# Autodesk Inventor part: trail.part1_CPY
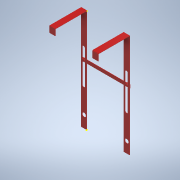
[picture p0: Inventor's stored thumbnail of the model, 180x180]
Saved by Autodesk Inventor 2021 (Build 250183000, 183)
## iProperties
Created: 2021-07
Part Number: trail.part1_CPY
Material: PMMA Plastic
Document SubType Name: Sheet Metal
Designer: CHIRAG
Density: 1.188 g/cm^3
Sheet Metal Rule: Default
Appearance: Red
Author: CHIRAG
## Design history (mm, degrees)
sketch "Sketch1"
  geometry: 1 further point
sketch "Sketch2"
  geometry: L1 (0, 0)-(-45.905, 0); L2 (-45.905, 0)-(-45.905, 801.589); L3 (-45.905, 801.589)-(0, 801.589); L4 (0, 801.589)-(0, 0)
  constraints: 8 end point, 2 parallel, 1 horizontal, 1 perpendicular
extrude "Extrusion1" new body sketch "Sketch2" distance "d0" = 3; taper "d1" = 0 deg
sketch "Sketch6"
  geometry: C1 r 15 at (-21.624, 91.104); 1 further point
  constraints: 1 centre point
  dimensions: "d12" = 30 diameter of C1
extrude "Extrusion4" cut sketch "Sketch6" distance "d13" = 3; taper "d14" = 0 deg
sketch "Sketch7"
  geometry: L1 (-24.46, 286.783)-(-24.46, 544.143); L2 (-45.905, 801.589)-(-45.905, 0) reference; L3 (-13.802, 286.783)-(-13.802, 544.143); L4 (-35.118, 544.143)-(-35.118, 286.783); A1 r 10.658 centre (-24.46, 286.783) between (-35.118, 286.783) and (-13.802, 286.783); A2 r 10.658 centre (-24.46, 544.143) between (-13.802, 544.143) and (-35.118, 544.143); 2 further points
  constraints: 8 end point, 4 point on circle, 4 tangent, 2 centre point, 2 parallel, 1 midpoint
extrude "Extrusion5" cut sketch "Sketch7" distance "d15" = 3; taper "d16" = 0 deg
sketch "Sketch9"
  geometry: 1 further point
sketch "Sketch10"
  geometry: 1 further point
sketch "Sketch11"
  geometry: L1 (45.905, 0)-(0, 0) reference; L2 (45.905, 0)-(0, 0); L3 (0, 0)-(0, -245.589); L4 (0, -245.589)-(45.905, -245.589); L5 (45.905, -245.589)-(45.905, 0); 1 further point
  constraints: 8 end point, 2 parallel, 1 horizontal, 1 perpendicular
extrude "Extrusion6" join sketch "Sketch11" distance "d17" = 3; taper "d18" = 0 deg
sketch "Sketch12"
  geometry: L1 (45.905, -801.589)-(45.905, 0) reference; L2 (0, 3)-(45.905, 3); L3 (45.905, 3)-(45.905, -45.6); L4 (45.905, -45.6)-(0, -45.6); L5 (0, -45.6)-(0, 3); 1 further point
  constraints: 8 end point, 2 parallel, 1 horizontal, 1 perpendicular, 1 point on line
extrude "Extrusion7" join sketch "Sketch12" distance "d19" = 3; taper "d20" = 0 deg
sketch "Sketch13"
  geometry: 1 further point
sketch "Sketch14"
  geometry: 1 further point
sketch "Sketch15"
  geometry: L1 (335.796, 0)-(289.84, 0); L2 (289.84, 0)-(289.84, 801.589); L3 (289.84, 801.589)-(335.796, 801.589); L4 (335.796, 801.589)-(335.796, 0); 1 further point
  constraints: 8 end point, 2 parallel, 1 horizontal, 1 perpendicular
extrude "Extrusion8" join sketch "Sketch15" distance "d21" = 3; taper "d22" = 0 deg
sketch "Sketch16"
  geometry: 1 further point
sketch "Sketch17"
  geometry: L1 (45.956, 0)-(0, 0) reference; L2 (45.956, 0)-(-2.159, 0); L3 (-2.159, 0)-(-2.159, -242.589); L4 (-2.159, -242.589)-(45.956, -242.589); L5 (45.956, -242.589)-(45.956, 0); 2 further points
  constraints: 8 end point, 2 parallel, 1 horizontal, 1 perpendicular
extrude "Extrusion9" join sketch "Sketch17" distance "d23" = 3; taper "d24" = 0 deg
sketch "Sketch18"
  geometry: L1 (48.115, -801.589)-(48.115, 0) reference; L2 (2.159, 0)-(2.159, -801.589) reference; L3 (48.115, 0)-(2.159, 0); L4 (2.159, 0)-(2.159, -48.926); L5 (2.159, -48.926)-(48.115, -48.926); L6 (48.115, -48.926)-(48.115, 0); 3 further points
  constraints: 8 end point, 2 parallel, 1 horizontal, 1 perpendicular, 1 point on line
extrude "Extrusion10" join sketch "Sketch18" distance "d25" = 3; taper "d26" = 0 deg
sketch "Sketch19"
  geometry: C1 r 15 at (313.555, 83.399); 1 further point
  constraints: 1 centre point
  dimensions: "d27" = 30 diameter of C1
extrude "Extrusion11" cut sketch "Sketch19" distance "d28" = 3; taper "d29" = 0 deg
sketch "Sketch20"
  geometry: 1 further point
sketch "Sketch21"
  geometry: L1 (311.674, 281.359)-(311.674, 547.037); L2 (322.359, 281.359)-(322.359, 547.037); L3 (300.989, 547.037)-(300.989, 281.359); A1 r 10.685 centre (311.674, 281.359) between (300.989, 281.359) and (322.359, 281.359); A2 r 10.685 centre (311.674, 547.037) between (322.359, 547.037) and (300.989, 547.037); 2 further points
  constraints: 8 end point, 4 point on circle, 4 tangent, 2 centre point, 1 midpoint, 1 parallel, 1 vertical
  dimensions: "d30" = 21.37 diameter of A2
extrude "Extrusion12" cut sketch "Sketch21" distance "d31" = 3; taper "d32" = 0 deg
sketch "Sketch22"
  geometry: L1 (-35.118, 286.783)-(-35.118, 544.143) reference; L2 (300.989, 547.037)-(300.989, 281.359) reference; C1 r 10.411 at (-24.707, 462.762); C2 r 10.661 at (311.651, 462.762); 1 further point
  constraints: 2 centre point, 2 tangent
extrude "Extrusion13" join sketch "Sketch22" stored distance "d33" = 12; taper "d34" = 0 deg
sketch "Sketch23"
  geometry: L1 (-335.796, 0)-(-335.796, 801.589) reference; L2 (45.905, 0)-(45.905, 804.589) reference; L3 (-335.796, 448.135)-(45.905, 448.135); L4 (45.905, 448.135)-(45.905, 473.43); L5 (45.905, 473.43)-(-335.796, 473.43); L6 (-335.796, 473.43)-(-335.796, 448.135); 3 further points
  constraints: 8 end point, 2 parallel, 2 point on line, 1 horizontal, 1 perpendicular
extrude "Extrusion14" join sketch "Sketch23" distance "d35" = 3; taper "d36" = 0 deg
body "Solid1"
other parameters: "Thickness" = 0.5, "KFactor" = 4.4, "BendRadius" = 0.5 (= Thickness), "BendReliefWidth" = 0.5 (= Thickness), "BendReliefDepth" = 0.25 (= 0.5 x Thickness), "CornerReliefSize" = 2 (= 4 x Thickness), "SeamGap" = 0.01, "MinimumRemnant" = 1 (= 2 x Thickness), "TransitionRadius" = 0.5 (= BendRadius), "JacobiRadiusSize" = 0.5 (= Thickness), "GapSize" = 0.5 (= Thickness), "d4" = 0.5 (= Thickness)
